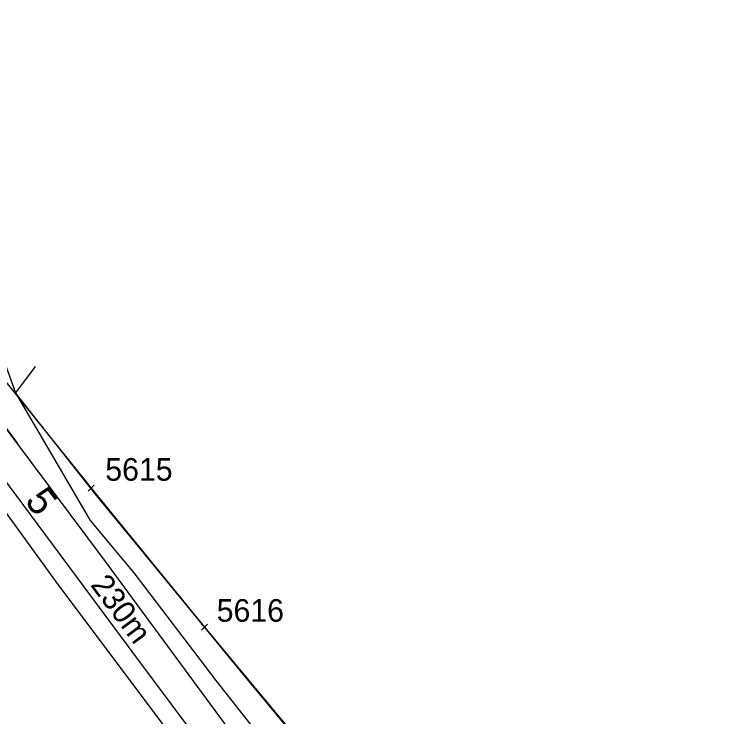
# Model space of a CAD drawing. Extents: x -804166 to -803706, y -1151030 to -1150147.
# Drawn here: x -803989.6 to -803925.7, y -1150318 to -1150255.9 of the extents above; entities that cross this region are included whole.
import ezdxf

# ---------------------------------------------------------------- set-up
doc = ezdxf.new("R2010")
doc.units = 0
for name, color, linetype in [('0381KM032-037P - Vrstva 1', 7, 'Continuous'), ('0381KM032-037P - Vrstva 17', 7, 'Continuous'), ('0381KM032-037P - Vrstva 4', 7, 'Continuous'), ('0381KM032-037P - Vrstva 49', 7, 'Continuous'), ('0381KM032-037P - Vrstva 51', 7, 'Continuous'), ('szdc - hran DP', 7, 'Continuous'), ('szdc - szdc_cislo', 7, 'Continuous'), ('szdc - szdc_krizek', 7, 'Continuous')]:
    doc.layers.add(name, color=color, linetype=linetype)

msp = doc.modelspace()

# ---------------------------------------------------------------- linework, layer by layer
at = {"layer": '0381KM032-037P - Vrstva 1'}
msp.add_lwpolyline([(-804011.14, -1150262.39), (-804005.45, -1150273.41), (-803998.73, -1150284.85), (-803991.51, -1150295.63), (-803978.8, -1150312.77), (-803963.69, -1150332.99), (-803952.21, -1150348.36), (-803946.3, -1150356.39), (-803941.6, -1150363.14), (-803936.71, -1150370.83), (-803932.05, -1150378.84), (-803927.78, -1150386.91), (-803924.06, -1150395.18), (-803920.62, -1150403.65), (-803918.06, -1150410.86), (-803915.07, -1150420.32), (-803912.96, -1150427.25), (-803910.49, -1150435.34), (-803907.334, -1150445.05), (-803903.668, -1150454.381), (-803897.938, -1150464.596), (-803891.973, -1150476.598)], dxfattribs=at)
at = {"layer": '0381KM032-037P - Vrstva 17'}
msp.add_line((-803987.75, -1150286.992), (-803989.471, -1150289.341), dxfattribs=at)
msp.add_lwpolyline([(-803938.298, -1150351.657), (-803942.72, -1150346.43), (-803950.365, -1150337.112), (-803959.949, -1150325.566), (-803969.628, -1150313.893), (-803978.45, -1150303.107), (-803982.306, -1150298.435), (-803989.471, -1150289.341)], dxfattribs=at)
at = {"layer": '0381KM032-037P - Vrstva 4'}
msp.add_lwpolyline([(-804015.087, -1150257.699), (-804005.607, -1150276.645), (-803997.811, -1150289.613), (-803985.988, -1150305.967), (-803963.827, -1150335.545), (-803947.69, -1150357.387), (-803941.599, -1150366.016), (-803933.495, -1150379.543), (-803925.569, -1150395.827), (-803919.567, -1150411.363), (-803915.11, -1150425.701)], dxfattribs=at)
at = {"layer": '0381KM032-037P - Vrstva 49'}
for points in [[(-804010.873, -1150255.863), (-804001.608, -1150274.672), (-803994.699, -1150286.679), (-803981.461, -1150304.357), (-803936.046, -1150366.093), (-803921.768, -1150392.538), (-803912.222, -1150419.282), (-803908.812, -1150430.908)], [(-804010.873, -1150255.863), (-804010.873, -1150255.863), (-804001.645, -1150274.597), (-803994.857, -1150286.394), (-803989.305, -1150293.808), (-803989.412, -1150293.739)], [(-803998.251, -1150280.496), (-803991.69, -1150283.272), (-803989.471, -1150289.341)], [(-803989.471, -1150289.341), (-803982.88, -1150300.61), (-803979.03, -1150305.25), (-803971.78, -1150314.79), (-803959.62, -1150330.2), (-803952.37, -1150339.47), (-803944.88, -1150350.15), (-803937.924, -1150356.122), (-803929.733, -1150361.392)]]:
    msp.add_lwpolyline(points, dxfattribs=at)
at = {"layer": '0381KM032-037P - Vrstva 51'}
msp.add_lwpolyline([(-804015.087, -1150257.699), (-804005.607, -1150276.645), (-803997.811, -1150289.613), (-803985.988, -1150305.967), (-803963.827, -1150335.545), (-803947.69, -1150357.387), (-803941.599, -1150366.016), (-803933.495, -1150379.543), (-803925.569, -1150395.827), (-803919.567, -1150411.363), (-803915.11, -1150425.701)], dxfattribs=at)
at = {"layer": 'szdc - hran DP'}
for p, q in [((-803997.02, -1150280.06), (-803982.8, -1150297.76)), ((-803982.8, -1150297.76), (-803972.77, -1150310.06)), ((-803972.77, -1150310.06), (-803951.37, -1150335.75))]:
    msp.add_line(p, q, dxfattribs=at)
at = {"layer": 'szdc - szdc_krizek'}
for p, q in [((-803982.535, -1150298.025), (-803983.066, -1150297.495)), ((-803983.066, -1150298.025), (-803982.535, -1150297.495)), ((-803972.505, -1150310.325), (-803973.036, -1150309.795)), ((-803973.036, -1150310.325), (-803972.505, -1150309.795))]:
    msp.add_line(p, q, dxfattribs=at)

# ---------------------------------------------------------------- texts
at = {"layer": '0381KM032-037P - Vrstva 1'}
for s, height, rotation, p in [('5', 2.5, 307.30884, (-803988.728, -1150298.918)), ('230m', 2, 306.55842, (-803982.916, -1150306.33))]:
    msp.add_text(s, height=height, rotation=rotation, dxfattribs=at).set_placement(p)
at = {"layer": 'szdc - szdc_cislo'}
for s, p in [('5615', (-803981.546, -1150297.104)), ('5616', (-803971.698, -1150309.579))]:
    msp.add_text(s, height=2, dxfattribs=at).set_placement(p)

doc.saveas('drawing.dxf')
